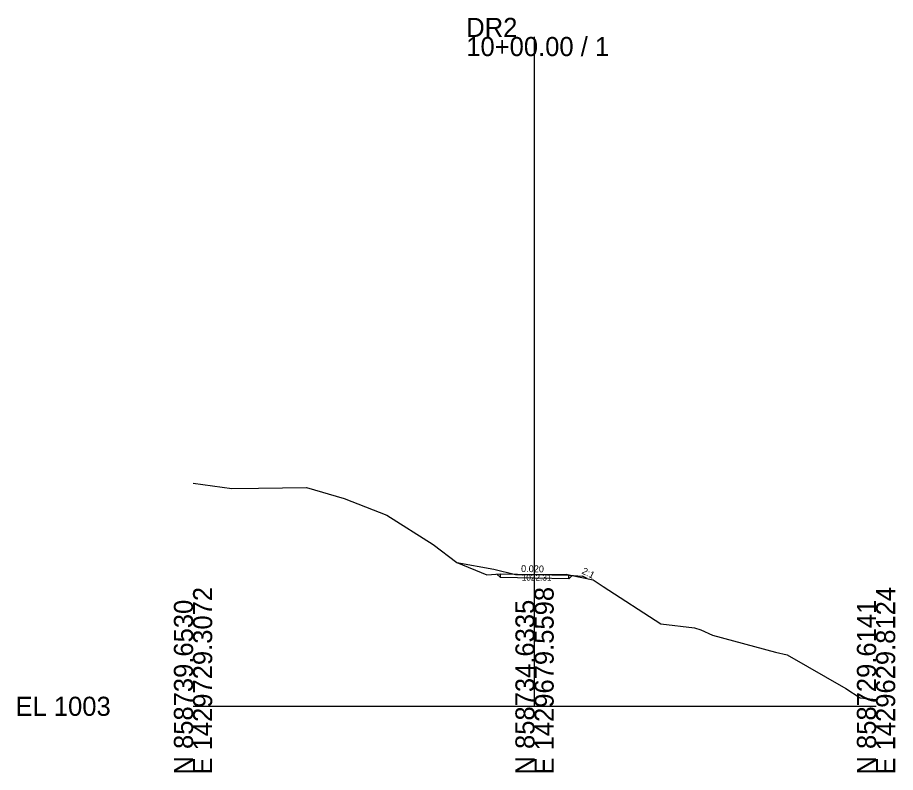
# Model space of a CAD drawing. Extents: x -26 to 103, y -10 to 3026.
# Drawn here: x -25.7 to 102.8, y -9.7 to 100.9 of the extents above; entities that cross this region are included whole.
import ezdxf

# ---------------------------------------------------------------- set-up
doc = ezdxf.new("R2010")
doc.units = 0
for name, color, linetype in [('Exist Cross Section Cell', 7, 'Continuous'), ('Exist XS Center Line Elevation Label', 7, 'Continuous'), ('Exist XS Ground Line', 7, 'Continuous'), ('Prop CMT Pvmt Surface', 7, 'Continuous'), ('Prop CMT Shld Paved Course 1', 7, 'Continuous'), ('Prop CMT Slope Grass', 7, 'Continuous'), ('Prop CMT Subgrade Earthwork', 7, 'Continuous'), ('Prop CMT Template Flag', 7, 'Continuous'), ('Prop XS SE Text', 7, 'Continuous'), ('Prop XS Side Slope Text', 7, 'Continuous')]:
    doc.layers.add(name, color=color, linetype=linetype)

msp = doc.modelspace()

# ---------------------------------------------------------------- linework, layer by layer
at = {"layer": 'Exist Cross Section Cell'}
for p, q in [((50, 0), (50, 98.05)), ((0, 0), (50, 0)), ((50, 0), (100, 0))]:
    msp.add_line(p, q, dxfattribs=at)
at = {"layer": 'Exist XS Ground Line'}
msp.add_lwpolyline([(0, 32.68), (5.68, 31.92), (9.6, 31.94), (16.61, 32.07), (22.15, 30.42), (28.39, 28.01), (35.18, 23.69), (38.61, 21.04), (44.03, 20.08), (47.23, 19.29), (50, 19.31), (54.64, 19.34), (55.28, 19.23), (58.59, 18.51), (60.06, 17.55), (68.5, 12.06), (73.42, 11.5), (74.34, 11.18), (76.04, 10.41), (85.3, 7.92), (87.01, 7.54), (95.57, 2.6), (97.67, 1.25), (100, 0.98)], dxfattribs=at)
at = {"layer": 'Prop CMT Pvmt Surface'}
for p, q in [((45, 19.41), (50, 19.31)), ((50, 19.31), (55, 19.21))]:
    msp.add_line(p, q, dxfattribs=at)
at = {"layer": 'Prop CMT Shld Paved Course 1'}
for points in [[(45, 18.87), (45, 19.41)], [(55, 18.67), (55, 19.21)]]:
    msp.add_lwpolyline(points, dxfattribs=at)
at = {"layer": 'Prop CMT Slope Grass'}
for p, q in [((38.61, 21.04), (43, 19.25)), ((43, 19.25), (45, 19.41)), ((55, 19.21), (57, 19.05)), ((57.69, 18.71), (57, 19.05))]:
    msp.add_line(p, q, dxfattribs=at)
at = {"layer": 'Prop CMT Subgrade Earthwork'}
for points in [[(45, 18.87), (44.5, 19.37)], [(55, 18.67), (55.5, 19.17)]]:
    msp.add_lwpolyline(points, dxfattribs=at)
at = {"layer": 'Prop CMT Template Flag'}
for p, q in [((50, 18.77), (45, 18.87)), ((55, 18.67), (50, 18.77))]:
    msp.add_line(p, q, dxfattribs=at)

# ---------------------------------------------------------------- texts
at = {"layer": 'Exist Cross Section Cell'}
for s, p in [('DR2', (40, 98.05)), ('10+00.00 / 1', (40, 95.25)), ('EL 1003', (-26, -1.4))]:
    msp.add_text(s, height=2.8, dxfattribs=at).set_placement(p)
for s, p in [('E 1429729.3072', (2.8, -10)), ('E 1429679.5598', (52.8, -10)), ('E 1429629.8124', (102.8, -10)), ('N 858739.6530', (0, -10)), ('N 858734.6335', (50, -10)), ('N 858729.6141', (100, -10))]:
    msp.add_text(s, height=2.8, rotation=90, dxfattribs=at).set_placement(p)
at = {"layer": 'Exist XS Center Line Elevation Label'}
msp.add_text('1022.31', height=0.9, dxfattribs=at).set_placement((48.13, 18.41))
at = {"layer": 'Prop XS SE Text'}
msp.add_text('0.020', height=1, rotation=358.8542, dxfattribs=at).set_placement((48.02, 19.68))
at = {"layer": 'Prop XS Side Slope Text'}
msp.add_text('2:1', height=1, rotation=333.4349, dxfattribs=at).set_placement((56.83, 19.49))

doc.saveas('drawing.dxf')
